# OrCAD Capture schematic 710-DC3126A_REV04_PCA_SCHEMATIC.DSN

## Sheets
1 PAGE1
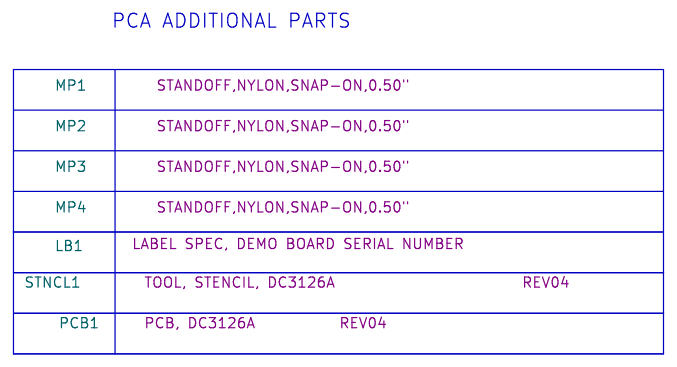
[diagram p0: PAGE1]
2 LT8686S: size Custom; title: MONOLITHIC STEP-DOWN REGULATOR; note: 42V QUAD, GANGABLE, SYNCHRONOUS
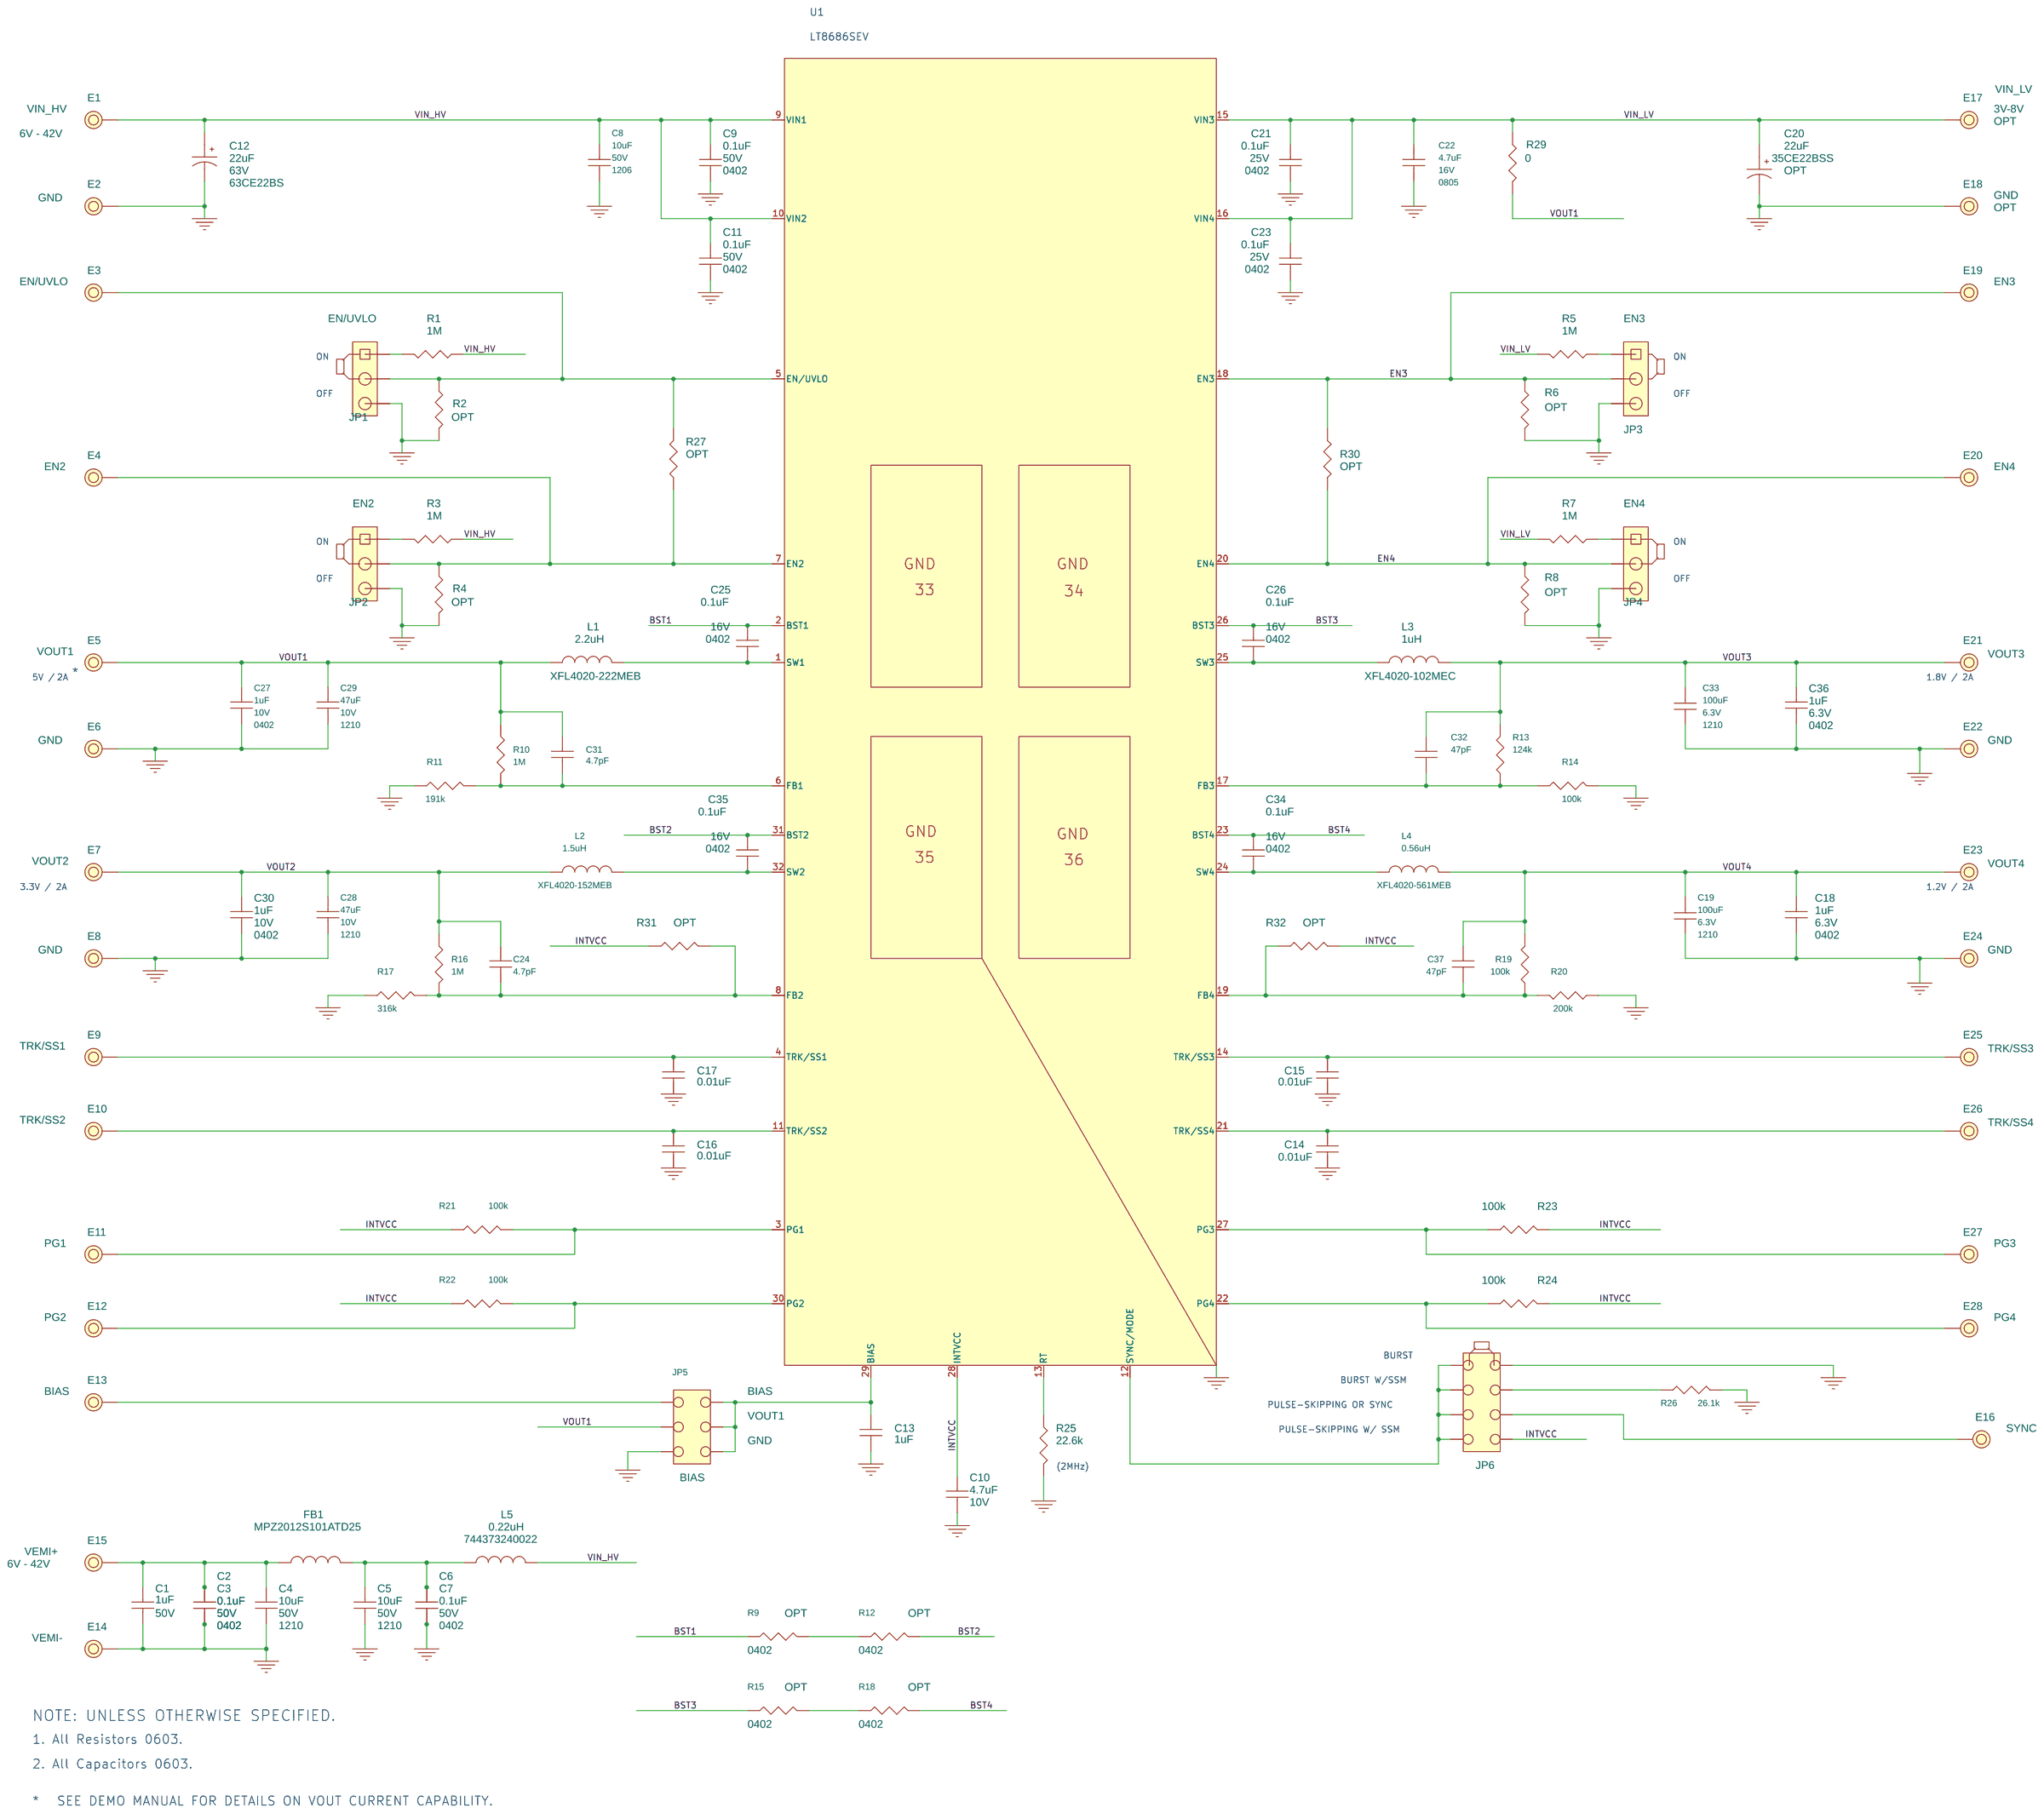
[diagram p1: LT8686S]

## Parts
sheet LT8686S
C1  1uF  [CC0603N]
C2  0.1uF  [CC0402N]
C3  0.1uF  [CC0402N]
C4  10uF  [CC1210N]
C5  10uF  [CC1210N]
C6  0.1uF  [CC0402N]
C7  0.1uF  [CC0402N]
C8  10uF  [CC1206N]
C9  0.1uF  [CC0402N]
C10  4.7uF  [CC0603N]
C11  0.1uF  [CC0402N]
C12  22uF  [SUNCON_CE-BS_6.3X7.7]
C13  1uF  [CC0603N]
C14  0.01uF  [CC0603N]
C15  0.01uF  [CC0603N]
C16  0.01uF  [CC0603N]
C17  0.01uF  [CC0603N]
C18  1uF  [CC0402N]
C19  100uF  [CC1210N]
C20  22uF  [SUNCON_CE-BSS_5X5.4]
C21  0.1uF  [CC0402N]
C22  4.7uF  [CC0805N]
C23  0.1uF  [CC0402N]
C24  4.7pF  [CC0603N]
C25  0.1uF  [CC0402N]
C26  0.1uF  [CC0402N]
C27  1uF  [CC0402N]
C28  47uF  [CC1210N]
C29  47uF  [CC1210N]
C30  1uF  [CC0402N]
C31  4.7pF  [CC0603N]
C32  47pF  [CC0603N]
C33  100uF  [CC1210N]
C34  0.1uF  [CC0402N]
C35  0.1uF  [CC0402N]
C36  1uF  [CC0402N]
C37  47pF  [CC0603N]
E1  TEST POINT  [MILLMAX2501]
E2  TEST POINT  [MILLMAX2501]
E3  TEST POINT  [MILLMAX2501]
E4  TEST POINT  [MILLMAX2501]
E5  TEST POINT  [MILLMAX2501]
E6  TEST POINT  [MILLMAX2501]
E7  TEST POINT  [MILLMAX2501]
E8  TEST POINT  [MILLMAX2501]
E9  TEST POINT  [MILLMAX2501]
E10  TEST POINT  [MILLMAX2501]
E11  TEST POINT  [MILLMAX2501]
E12  TEST POINT  [MILLMAX2501]
E13  TEST POINT  [MILLMAX2501]
E14  TEST POINT  [MILLMAX2501]
E15  TEST POINT  [MILLMAX2501]
E16  TEST POINT  [MILLMAX2501]
E17  TEST POINT  [MILLMAX2501]
E18  TEST POINT  [MILLMAX2501]
E19  TEST POINT  [MILLMAX2501]
E20  TEST POINT  [MILLMAX2501]
E21  TEST POINT  [MILLMAX2501]
E22  TEST POINT  [MILLMAX2501]
E23  TEST POINT  [MILLMAX2501]
E24  TEST POINT  [MILLMAX2501]
E25  TEST POINT  [MILLMAX2501]
E26  TEST POINT  [MILLMAX2501]
E27  TEST POINT  [MILLMAX2501]
E28  TEST POINT  [MILLMAX2501]
FB1  100 OHMS @100MHz  [IND0805N]
JP1  HDR  [HD1X3-079]
JP2  HDR  [HD1X3-079]
JP3  HDR  [HD1X3-079]
JP4  HDR  [HD1X3-079]
JP5  HDR  [HD2X3-079]
JP6  HDR  [HD2X4-079]
L1  2.2uH  [COILCRAFT-XFL4020]
L2  1.5uH  [COILCRAFT-XFL4020]
L3  1uH  [COILCRAFT-XFL4020]
L4  0.56uH  [COILCRAFT-XFL4020]
L5  0.22uH  [WURTH-4020]
R1  1M  [CR0603N]
R2  OPT  [CR0603N]
R3  1M  [CR0603N]
R4  OPT  [CR0603N]
R5  1M  [CR0603N]
R6  OPT  [CR0603N]
R7  1M  [CR0603N]
R8  OPT  [CR0603N]
R9  OPT  [CR0402N]
R10  1M  [CR0603N]
R11  191k  [CR0603N]
R12  OPT  [CR0402N]
R13  124k  [CR0603N]
R14  100k  [CR0603N]
R15  OPT  [CR0402N]
R16  1M  [CR0603N]
R17  316k  [CR0603N]
R18  OPT  [CR0402N]
R19  100k  [CR0603N]
R20  200k  [CR0603N]
R21  100k  [CR0603N]
R22  100k  [CR0603N]
R23  100k  [CR0603N]
R24  100k  [CR0603N]
R25  22.6k  [CR0603N]
R26  26.1k  [CR0603N]
R27  OPT  [CR0603N]
R29  0  [VISHAY-WSL_9-0603]
R30  OPT  [CR0603N]
R31  0  [CR0603N]
R32  0  [CR0603N]
U1  LT8686SEV  [LTC-LQFN-32-1680]
XJP1  SHUNT
XJP2  SHUNT
XJP3  SHUNT
XJP4  SHUNT
XJP5  SHUNT
XJP6  SHUNT
sheet PAGE1
LB1  LABEL  [895-0154_REV01]
MP1  STANDOFF  [KEYSTONE_8829-8834]
MP2  STANDOFF  [KEYSTONE_8829-8834]
MP3  STANDOFF  [KEYSTONE_8829-8834]
MP4  STANDOFF  [KEYSTONE_8829-8834]
PCB1  PCB, DC3126A
STNCL1  TOOL, STENCIL, DC3126A

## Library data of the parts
C1 C13 = CAP: CAP.,1uF,X5R,50V,10%,0603,AEC-Q200, NO SUBS. ALLOWED; CLASS: DISCRETE; Dielectric Type: X5R; FPLIST: CC0603N,CC0603L,CC0603M; Inventory Qty: 19670; Manufacturer: MURATA; Manufacturer PN: GRT188R61H105KE13D; PART_NUMBER: 150-0686; Package Size: 0603; Package Type: SMD; Rated Voltage: 50V; Tolerance: 10%
C2 C3 C6 C7 C9 C11 = CAP: CAP.,0.1uF,X7R,50V,10%,0402,AEC-Q200, NO SUBS. ALLOWED; CLASS: DISCRETE; Dielectric Type: X7R; FPLIST: CC0402N,CC0402L,CC0402M; Inventory Qty: 11376; Manufacturer: MURATA; Manufacturer PN: GCM155R71H104KE02D; PART_NUMBER: 150-2353; Package Size: 0402; Rated Voltage: 50V; Tolerance: 10%
C4 C5 = CAP: CAP.,10uF,X7R,50V,10%,1210,NO SUBS. ALLOWED; CLASS: DISCRETE; Dielectric Type: X7R; FPLIST: CC1210N,CC1210L,CC1210M; Inventory Qty: 191942; Manufacturer: MURATA; Manufacturer PN: GRM32ER71H106KA12L; PART_NUMBER: 150-3043; Package Size: 1210; Package Type: SMD; Rated Voltage: 50V; Tolerance: 10%
C8 = CAP: CAP.,10uF,X7R,50V,10%,1206; CLASS: DISCRETE; Dielectric Type: X7R; FPLIST: CC1206N,CC1206L,CC1206M; Inventory Qty: 4760; Manufacturer: SAMSUNG; Manufacturer PN: CL31B106KBHNNNE; PART_NUMBER: 150-1796; Package Size: 1206; Package Type: SMD; Rated Voltage: 50V; Tolerance: 10%
C10 = CAP: CAP.,4.7uF,X5R,10V,10%,0603; CLASS: DISCRETE; Dielectric Type: X5R; FPLIST: CC0603N,CC0603L,CC0603M; Inventory Qty: 20774; Manufacturer: AVX; Manufacturer PN: 0603ZD475KAT2A; PART_NUMBER: 150-3050; Package Size: 0603; Rated Voltage: 10V; Tolerance: 10%
C12 = CAP_P: CAP.,22uF,ALUM ELECT,63V,20%,6.3x7.7mm,SMD,RADIAL,CE-BS Series,AEC-Q200; CLASS: DISCRETE; Dielectric Type: ALUM ELECT; FPLIST: SUNCON_CE-BS_6.3X7.7,SUNCON_CE-BS_6-3X7-7; Inventory Qty: 35661; Manufacturer: SUN ELECTRONIC INDUSTRIES CORP; Manufacturer PN: 63CE22BS; PART_NUMBER: 150-3334; Package Size: 6.3x7.7mm,SMD,RADIAL; Rated Voltage: 63V; Tolerance: 20%
C14-C17 = CAP: CAP.,0.01uF,X7R,25V,10%,0603; CLASS: DISCRETE; Dielectric Type: X7R; FPLIST: CC0603N,CC0603L,CC0603M; Inventory Qty: 51504; Manufacturer: AVX; Manufacturer PN: 06033C103KAT2A; PART_NUMBER: 150-3341; Package Size: 0603; Package Type: SMD; Rated Voltage: 25V; Tolerance: 10%
C18 C36 = CAP: CAP.,1uF,X7R,6.3V,10%,0402; CLASS: DISCRETE; Dielectric Type: X7R; FPLIST: CC0402N,CC0402L,CC0402M; Inventory Qty: 20000; Manufacturer: MURATA; Manufacturer PN: GRM155R70J105KA12D; PART_NUMBER: 150-2328; Package Size: 0402; Rated Voltage: 6.3V; Tolerance: 10%
C19 C33 = CAP: CAP.,100uF,X7S,6.3V,20%,1210; CLASS: DISCRETE; Dielectric Type: X7S; FPLIST: CC1210N,CC1210L,CC1210M; Inventory Qty: 500; Manufacturer: MURATA; Manufacturer PN: GRM32EC70J107ME15L; PART_NUMBER: 150-2396; Package Size: 1210; Rated Voltage: 6.3V; Temperature Coefficient: X7S; Tolerance: 20%
C20 = CAP_P: CAP.,22uF,35V,20%,5x5.4mm,SMD,RADIAL,CE-BSS Series,AEC-Q200; BOM Notes: OPT; CLASS: DISCRETE; Dielectric Type: ALUM ELECT; FPLIST: SUNCON_CE-BSS_5X5.4,SUNCON_CE-BSS_5X5-4; Inventory Qty: 8056; Manufacturer: SUN ELECTRONIC INDUSTRIES CORP; Manufacturer PN: 35CE22BSS; PART_NUMBER: 150-0491; Package Size: 5x5.4mm,SMD,RADIAL; Rated Voltage: 35V; Tolerance: 20%
C21 C23 = CAP: CAP.,0.1uF,X7R,25V,10%,0402,AEC-Q200; CLASS: DISCRETE; Dielectric Type: X7R; FPLIST: CC0402N,CC0402L,CC0402M; Inventory Qty: 22030; Manufacturer: MURATA; Manufacturer PN: GCM155R71E104KE02D; PART_NUMBER: 150-1756; Package Size: 0402; Rated Voltage: 25V; Temperature Coefficient: X7R; Tolerance: 10%
C22 = CAP: CAP.,4.7uF,X7R,16V,20%,0805,AEC-Q200; CLASS: DISCRETE; Dielectric Type: X7R; FPLIST: CC0805N,CC0805L,CC0805M; Inventory Qty: 0; Manufacturer: Taiyo Yuden; Manufacturer PN: MCASE21GAB7475MTNA01; PART_NUMBER: 150-1025; Package Size: 0805; Rated Voltage: 16V; Tolerance: 20%
C24 C31 = CAP: CAP.,4.7pF,C0G,25V,10%,0603; CLASS: DISCRETE; Dielectric Type: C0G; FPLIST: CC0603N,CC0603L,CC0603M; Inventory Qty: 24942; Manufacturer: AVX; Manufacturer PN: 06033A4R7KAT2A; PART_NUMBER: 150-0381; Package Size: 0603; Rated Voltage: 25V; Tolerance: 10%
C25 C26 C34 C35 = CAP: CAP.,0.1uF,X7R,16V,10%,0402,AEC-Q200; CLASS: DISCRETE; Dielectric Type: X7R; FPLIST: CC0402N,CC0402L,CC0402M; Inventory Qty: 23025; Manufacturer: MURATA; Manufacturer PN: GCM155R71C104KA55D; PART_NUMBER: 150-0506; Package Size: 0402; Rated Voltage: 16V; Tolerance: 10%
C27 C30 = CAP: CAP.,1uF,X5R,10V,10%,0402; CLASS: DISCRETE; Dielectric Type: X5R; FPLIST: CC0402N,CC0402L,CC0402M; Inventory Qty: 110817; Manufacturer: MURATA; Manufacturer PN: GRM155R61A105KE15D; PART_NUMBER: 150-3493; Package Size: 0402; Rated Voltage: 10V; Tolerance: 10%
C28 C29 = CAP: CAP.,47uF,X7R,10V,10%,1210,NO SUBS. ALLOWED; CLASS: DISCRETE; Dielectric Type: X7R; FPLIST: CC1210N,CC1210L,CC1210M; Inventory Qty: 0; Manufacturer: MURATA; Manufacturer PN: GRM32ER71A476KE15L; PART_NUMBER: 150-0981; Package Size: 1210; Package Type: SMD; Part Reference_1: C255 (OPT); Rated Voltage: 10V; Tolerance: 10%
C32 C37 = CAP: CAP.,47pF,C0G,25V,10%,0603; CLASS: DISCRETE; Dielectric Type: C0G; FPLIST: CC0603N,CC0603L,CC0603M; Inventory Qty: 3750; Manufacturer: AVX; Manufacturer PN: 06033A470KAT2A; PART_NUMBER: 150-3110; Package Size: 0603; Rated Voltage: 25V; Tolerance: 10%
E1 = TESTPOINT_.219_MILL-MAX_2501: TEST POINT,TURRET,0.094" MTG. HOLE,PCB 0.062" THK; 10th Part Field: 10th???; 1th Part Field: 6V - 42V; 9th Part Field: VIN_HV; CLASS: IO; FPLIST: MILLMAX2501,MILLMAX2501-2; Inventory Qty: 823526; Manufacturer: MILL-MAX; Manufacturer PN: 2501-2-00-80-00-00-07-0; PART_NUMBER: 260-0003
E2 E6 E8 = TESTPOINT_.219_MILL-MAX_2501: TEST POINT,TURRET,0.094" MTG. HOLE,PCB 0.062" THK; 10th Part Field: 10th???; 9th Part Field: GND; CLASS: IO; FPLIST: MILLMAX2501,MILLMAX2501-2; Inventory Qty: 823526; Manufacturer: MILL-MAX; Manufacturer PN: 2501-2-00-80-00-00-07-0; PART_NUMBER: 260-0003
E3 = TESTPOINT_.219_MILL-MAX_2501: TEST POINT,TURRET,0.094" MTG. HOLE,PCB 0.062" THK; 10th Part Field: 10th???; 9th Part Field: EN/UVLO; CLASS: IO; FPLIST: MILLMAX2501,MILLMAX2501-2; Inventory Qty: 823526; Manufacturer: MILL-MAX; Manufacturer PN: 2501-2-00-80-00-00-07-0; PART_NUMBER: 260-0003
E4 = TESTPOINT_.219_MILL-MAX_2501: TEST POINT,TURRET,0.094" MTG. HOLE,PCB 0.062" THK; 10th Part Field: 10th???; 9th Part Field: EN2; CLASS: IO; FPLIST: MILLMAX2501,MILLMAX2501-2; Inventory Qty: 823526; Manufacturer: MILL-MAX; Manufacturer PN: 2501-2-00-80-00-00-07-0; PART_NUMBER: 260-0003
E5 = TESTPOINT_.219_MILL-MAX_2501: TEST POINT,TURRET,0.094" MTG. HOLE,PCB 0.062" THK; 10th Part Field: 10th???; 9th Part Field: VOUT1; CLASS: IO; FPLIST: MILLMAX2501,MILLMAX2501-2; Inventory Qty: 823526; Manufacturer: MILL-MAX; Manufacturer PN: 2501-2-00-80-00-00-07-0; PART_NUMBER: 260-0003
E7 = TESTPOINT_.219_MILL-MAX_2501: TEST POINT,TURRET,0.094" MTG. HOLE,PCB 0.062" THK; 10th Part Field: 10th???; 9th Part Field: VOUT2; CLASS: IO; FPLIST: MILLMAX2501,MILLMAX2501-2; Inventory Qty: 823526; Manufacturer: MILL-MAX; Manufacturer PN: 2501-2-00-80-00-00-07-0; PART_NUMBER: 260-0003
E9 = TESTPOINT_.219_MILL-MAX_2501: TEST POINT,TURRET,0.094" MTG. HOLE,PCB 0.062" THK; 10th Part Field: 10th???; 9th Part Field: TRK/SS1; CLASS: IO; FPLIST: MILLMAX2501,MILLMAX2501-2; Inventory Qty: 823526; Manufacturer: MILL-MAX; Manufacturer PN: 2501-2-00-80-00-00-07-0; PART_NUMBER: 260-0003
E10 = TESTPOINT_.219_MILL-MAX_2501: TEST POINT,TURRET,0.094" MTG. HOLE,PCB 0.062" THK; 10th Part Field: 10th???; 9th Part Field: TRK/SS2; CLASS: IO; FPLIST: MILLMAX2501,MILLMAX2501-2; Inventory Qty: 823526; Manufacturer: MILL-MAX; Manufacturer PN: 2501-2-00-80-00-00-07-0; PART_NUMBER: 260-0003
E11 = TESTPOINT_.219_MILL-MAX_2501: TEST POINT,TURRET,0.094" MTG. HOLE,PCB 0.062" THK; 10th Part Field: 10th???; 9th Part Field: PG1; CLASS: IO; FPLIST: MILLMAX2501,MILLMAX2501-2; Inventory Qty: 823526; Manufacturer: MILL-MAX; Manufacturer PN: 2501-2-00-80-00-00-07-0; PART_NUMBER: 260-0003
E12 = TESTPOINT_.219_MILL-MAX_2501: TEST POINT,TURRET,0.094" MTG. HOLE,PCB 0.062" THK; 10th Part Field: 10th???; 9th Part Field: PG2; CLASS: IO; FPLIST: MILLMAX2501,MILLMAX2501-2; Inventory Qty: 823526; Manufacturer: MILL-MAX; Manufacturer PN: 2501-2-00-80-00-00-07-0; PART_NUMBER: 260-0003
E13 = TESTPOINT_.219_MILL-MAX_2501: TEST POINT,TURRET,0.094" MTG. HOLE,PCB 0.062" THK; 10th Part Field: 10th???; 9th Part Field: BIAS; CLASS: IO; FPLIST: MILLMAX2501,MILLMAX2501-2; Inventory Qty: 823526; Manufacturer: MILL-MAX; Manufacturer PN: 2501-2-00-80-00-00-07-0; PART_NUMBER: 260-0003
E14 = TESTPOINT_.219_MILL-MAX_2501: TEST POINT,TURRET,0.094" MTG. HOLE,PCB 0.062" THK; 10th Part Field: 10th???; 9th Part Field: VEMI-; CLASS: IO; FPLIST: MILLMAX2501,MILLMAX2501-2; Inventory Qty: 823526; Manufacturer: MILL-MAX; Manufacturer PN: 2501-2-00-80-00-00-07-0; PART_NUMBER: 260-0003
E15 = TESTPOINT_.219_MILL-MAX_2501: TEST POINT,TURRET,0.094" MTG. HOLE,PCB 0.062" THK; 10th Part Field: 10th???; 1th Part Field: 6V - 42V; 9th Part Field: VEMI+; CLASS: IO; FPLIST: MILLMAX2501,MILLMAX2501-2; Inventory Qty: 823526; Manufacturer: MILL-MAX; Manufacturer PN: 2501-2-00-80-00-00-07-0; PART_NUMBER: 260-0003
E16 = TESTPOINT_.219_MILL-MAX_2501: TEST POINT,TURRET,0.094" MTG. HOLE,PCB 0.062" THK; 10th Part Field: 10th???; 1th Part Field: 3V - 8V; 9th Part Field: SYNC; CLASS: IO; FPLIST: MILLMAX2501,MILLMAX2501-2; Inventory Qty: 823526; Manufacturer: MILL-MAX; Manufacturer PN: 2501-2-00-80-00-00-07-0; PART_NUMBER: 260-0003
E17 = TESTPOINT_.219_MILL-MAX_2501: TEST POINT,TURRET,0.094" MTG. HOLE,PCB 0.062" THK; 10th Part Field: 10th???; 1ST PART FIELD: OPT; 1th Part Field: 3V-8V; 9th Part Field: VIN_LV; CLASS: IO; FPLIST: MILLMAX2501,MILLMAX2501-2; Inventory Qty: 823526; Manufacturer: MILL-MAX; Manufacturer PN: 2501-2-00-80-00-00-07-0; PART_NUMBER: 260-0003
E18 = TESTPOINT_.219_MILL-MAX_2501: TEST POINT,TURRET,0.094" MTG. HOLE,PCB 0.062" THK; 10th Part Field: 10th???; 1ST PART FIELD: OPT; 9th Part Field: GND; CLASS: IO; FPLIST: MILLMAX2501,MILLMAX2501-2; Inventory Qty: 823526; Manufacturer: MILL-MAX; Manufacturer PN: 2501-2-00-80-00-00-07-0; PART_NUMBER: 260-0003
E19 = TESTPOINT_.219_MILL-MAX_2501: TEST POINT,TURRET,0.094" MTG. HOLE,PCB 0.062" THK; 10th Part Field: 10th???; 9th Part Field: EN3; CLASS: IO; FPLIST: MILLMAX2501,MILLMAX2501-2; Inventory Qty: 823526; Manufacturer: MILL-MAX; Manufacturer PN: 2501-2-00-80-00-00-07-0; PART_NUMBER: 260-0003
E20 = TESTPOINT_.219_MILL-MAX_2501: TEST POINT,TURRET,0.094" MTG. HOLE,PCB 0.062" THK; 10th Part Field: 10th???; 1th Part Field: 3V - 8V; 9th Part Field: EN4; CLASS: IO; FPLIST: MILLMAX2501,MILLMAX2501-2; Inventory Qty: 823526; Manufacturer: MILL-MAX; Manufacturer PN: 2501-2-00-80-00-00-07-0; PART_NUMBER: 260-0003
E21 = TESTPOINT_.219_MILL-MAX_2501: TEST POINT,TURRET,0.094" MTG. HOLE,PCB 0.062" THK; 10th Part Field: 10th???; 1th Part Field: 3V - 8V; 9th Part Field: VOUT3; CLASS: IO; FPLIST: MILLMAX2501,MILLMAX2501-2; Inventory Qty: 823526; Manufacturer: MILL-MAX; Manufacturer PN: 2501-2-00-80-00-00-07-0; PART_NUMBER: 260-0003
E22 E24 = TESTPOINT_.219_MILL-MAX_2501: TEST POINT,TURRET,0.094" MTG. HOLE,PCB 0.062" THK; 10th Part Field: 10th???; 1th Part Field: 3V - 8V; 9th Part Field: GND; CLASS: IO; FPLIST: MILLMAX2501,MILLMAX2501-2; Inventory Qty: 823526; Manufacturer: MILL-MAX; Manufacturer PN: 2501-2-00-80-00-00-07-0; PART_NUMBER: 260-0003
E23 = TESTPOINT_.219_MILL-MAX_2501: TEST POINT,TURRET,0.094" MTG. HOLE,PCB 0.062" THK; 10th Part Field: 10th???; 1th Part Field: 3V - 8V; 9th Part Field: VOUT4; CLASS: IO; FPLIST: MILLMAX2501,MILLMAX2501-2; Inventory Qty: 823526; Manufacturer: MILL-MAX; Manufacturer PN: 2501-2-00-80-00-00-07-0; PART_NUMBER: 260-0003
E25 = TESTPOINT_.219_MILL-MAX_2501: TEST POINT,TURRET,0.094" MTG. HOLE,PCB 0.062" THK; 10th Part Field: 10th???; 1th Part Field: 3V - 8V; 9th Part Field: TRK/SS3; CLASS: IO; FPLIST: MILLMAX2501,MILLMAX2501-2; Inventory Qty: 823526; Manufacturer: MILL-MAX; Manufacturer PN: 2501-2-00-80-00-00-07-0; PART_NUMBER: 260-0003
E26 = TESTPOINT_.219_MILL-MAX_2501: TEST POINT,TURRET,0.094" MTG. HOLE,PCB 0.062" THK; 10th Part Field: 10th???; 1th Part Field: 3V - 8V; 9th Part Field: TRK/SS4; CLASS: IO; FPLIST: MILLMAX2501,MILLMAX2501-2; Inventory Qty: 823526; Manufacturer: MILL-MAX; Manufacturer PN: 2501-2-00-80-00-00-07-0; PART_NUMBER: 260-0003
E27 = TESTPOINT_.219_MILL-MAX_2501: TEST POINT,TURRET,0.094" MTG. HOLE,PCB 0.062" THK; 10th Part Field: 10th???; 1th Part Field: 3V - 8V; 9th Part Field: PG3; CLASS: IO; FPLIST: MILLMAX2501,MILLMAX2501-2; Inventory Qty: 823526; Manufacturer: MILL-MAX; Manufacturer PN: 2501-2-00-80-00-00-07-0; PART_NUMBER: 260-0003
E28 = TESTPOINT_.219_MILL-MAX_2501: TEST POINT,TURRET,0.094" MTG. HOLE,PCB 0.062" THK; 10th Part Field: 10th???; 1th Part Field: 3V - 8V; 9th Part Field: PG4; CLASS: IO; FPLIST: MILLMAX2501,MILLMAX2501-2; Inventory Qty: 823526; Manufacturer: MILL-MAX; Manufacturer PN: 2501-2-00-80-00-00-07-0; PART_NUMBER: 260-0003
FB1 = IND: IND.,100 OHMS @100MHz,FERRITE BEAD,25%,4A,20mOHMS,0805,AEC-Q200; CLASS: DISCRETE; FPLIST: IND0805N,IND0805L,IND0805M; Inventory Qty: 0; Manufacturer: TDK; Manufacturer PN: MPZ2012S101ATD25; PART_NUMBER: 200-0403; Package Size: 0805; Tolerance: 25%
JP1 = 1X3_B: CONN.,HDR,MALE,1x3,2mm,VERT,ST,THT,NO SUBS. ALLOWED; 9th Part Field: EN/UVLO; CLASS: IO; Inventory Qty: 28997; Manufacturer: Wurth Elektronik; Manufacturer PN: 62000311121; PART_NUMBER: 250-0639
JP2 = 1X3_B: CONN.,HDR,MALE,1x3,2mm,VERT,ST,THT,NO SUBS. ALLOWED; 9th Part Field: EN2; CLASS: IO; Inventory Qty: 28997; Manufacturer: Wurth Elektronik; Manufacturer PN: 62000311121; PART_NUMBER: 250-0639
JP3 = 1X3_B: CONN.,HDR,MALE,1x3,2mm,VERT,ST,THT,NO SUBS. ALLOWED; 9th Part Field: EN3; CLASS: IO; Inventory Qty: 28997; Manufacturer: Wurth Elektronik; Manufacturer PN: 62000311121; PART_NUMBER: 250-0639
JP4 = 1X3_B: CONN.,HDR,MALE,1x3,2mm,VERT,ST,THT,NO SUBS. ALLOWED; 9th Part Field: EN4; CLASS: IO; Inventory Qty: 28997; Manufacturer: Wurth Elektronik; Manufacturer PN: 62000311121; PART_NUMBER: 250-0639
JP5 = HEADER_2X3_.079: CONN.,HDR,MALE,2x3,2mm,VERT,ST,THT; 1st Part Field: BIAS; 2nd Part Field: BIAS; 3rd Part Field: VOUT1; 4th Part Field: GND; CLASS: IO; Inventory Qty: 17651; Manufacturer: WURTH ELEKTRONIK; Manufacturer PN: 62000621121; PART_NUMBER: 250-0483
JP6 = HEADER_2X4_.079: CONN.,HDR,MALE,2x4,2mm,VERT,ST,THT; 1st Part Field: SYNC; CLASS: IO; Inventory Qty: 6305; Manufacturer: WURTH ELEKTRONIK; Manufacturer PN: 62000821121; PART_NUMBER: 250-0581
L1 = IND: IND.,2.2uH,PWR,SHIELDED,20%,8A,23.5mOHMS,4.3x4.3mm,AEC-Q200; CLASS: DISCRETE; Inventory Qty: 506; Manufacturer: COILCRAFT; Manufacturer PN: XFL4020-222MEB; PART_NUMBER: 200-0255; Package Size: 4.3x4.3mm; Tolerance: 20%
L2 = IND: IND.,1.5uH,PWR,20%,9.1A,15.8mOHMS,SMD,AEC-Q200,SHIELDED; CLASS: DISCRETE; Inventory Qty: 0; Manufacturer: COILCRAFT; Manufacturer PN: XFL4020-152MEB; PART_NUMBER: 200-0367; Package Size: SMD; Tolerance: 20%
L3 = IND: IND.,1uH,PWR,SHIELDED,20%,11A,11.9mOHMS,SMD,AEC-Q200; CLASS: DISCRETE; Inventory Qty: 0; Manufacturer: COILCRAFT; Manufacturer PN: XFL4020-102MEC; PART_NUMBER: 200-0404; Package Size: SMD; Tolerance: 20%
L4 = IND: IND.,0.56uH,PWR,20%,6A,5.53mOHMS,SMD,AEC-Q200; CLASS: DISCRETE; Inventory Qty: 0; Manufacturer: COILCRAFT; Manufacturer PN: XFL4020-561MEB; PART_NUMBER: 200-0421; Package Size: SMD; Tolerance: 20%
L5 = IND: IND.,0.22uH,PWR,SHIELDED,30%,9.5A,7.3mOHMS,4020; CLASS: DISCRETE; FPLIST: WURTH-4020,WURTH-744373240022; Inventory Qty: 418; Manufacturer: WURTH ELEKTRONIK; Manufacturer PN: 744373240022; PART_NUMBER: 200-0481; Package Size: 4020; Tolerance: 30%
R1 R3 R5 R7 R10 R16 = RES: RES.,1M OHM,1%,1/10W,0603; CLASS: DISCRETE; FPLIST: CR0603N,CR0603L,CR0603M; Inventory Qty: 165718; Manufacturer: VISHAY; Manufacturer PN: CRCW06031M00FKEA; PART_NUMBER: 100-0335; Package Size: 0603; Rated Power: 1/10W; Temperature Coefficient: 100ppm; Tolerance: 1%
R2 R4 R6 R8 R27 R30 = RES: RES., OPTION, 0603; CLASS: DISCRETE; FPLIST: CR0603N,CR0603L,CR0603M; PART_NUMBER: 100-2374; Package Size: 0603
R9 R12 R15 R18 = RES: RES., OPTION, 0402; CLASS: DISCRETE; FPLIST: CR0402N,CR0402L,CR0402M; PART_NUMBER: 100-0357; Package Size: 0402
R11 = RES: RES.,191k OHMS,1%,1/10W,0603,AEC-Q200; CLASS: DISCRETE; FPLIST: CR0603N,CR0603L,CR0603M; Inventory Qty: 10000; Manufacturer: KOA SPEER; Manufacturer PN: RK73H1JTTD1913F; PART_NUMBER: 100-1556; Package Size: 0603; Rated Power: 1/10W; Temperature Coefficient: +/-100ppm; Tolerance: 1%
R13 = RES: RES.,124k OHMS,1%,1/10W,0603,AEC-Q200; CLASS: DISCRETE; FPLIST: CR0603N,CR0603L,CR0603M; Inventory Qty: 90015; Manufacturer: PANASONIC; Manufacturer PN: ERJ3EKF1243V; PART_NUMBER: 100-0224; Package Size: 0603; Rated Power: 1/10W; Temperature Coefficient: 100ppm; Tolerance: 1%
R14 R19 R21-R24 = RES: RES.,100k OHMS,1%,1/10W,0603,AEC-Q200; CLASS: DISCRETE; FPLIST: CR0603N,CR0603L,CR0603M; Inventory Qty: 185604; Manufacturer: VISHAY; Manufacturer PN: CRCW0603100KFKEA; PART_NUMBER: 100-0343; Package Size: 0603; Rated Power: 1/10W; Temperature Coefficient: +/-100ppm; Tolerance: 1%
R17 = RES: RES.,316k OHMS,1%,1/10W,0603,AEC-Q200; CLASS: DISCRETE; FPLIST: CR0603N,CR0603L,CR0603M; Inventory Qty: 12794; Manufacturer: NIC; Manufacturer PN: NRC06F3163TRF; PART_NUMBER: 100-2591; Package Size: 0603; Rated Power: 1/10W; Temperature Coefficient: 100ppm; Tolerance: 1%
R20 = RES: RES.,200k OHMS,1%,1/10W,0603; CLASS: DISCRETE; FPLIST: CR0603N,CR0603L,CR0603M; Inventory Qty: 116370; Manufacturer: NIC; Manufacturer PN: NRC06F2003TRF; PART_NUMBER: 100-2378; Package Size: 0603; Rated Power: 1/10W; Temperature Coefficient: 100ppm/C; Tolerance: 1%
R25 = RES: RES.,22.6k OHMS,1%,1/10W,0603; CLASS: DISCRETE; FPLIST: CR0603N,CR0603L,CR0603M; Inventory Qty: 5000; Manufacturer: NIC; Manufacturer PN: NRC06F2262TRF; PART_NUMBER: 100-2365; Package Size: 0603; Rated Power: 1/10W; Temperature Coefficient: 100ppm/C; Tolerance: 1%
R26 = RES: RES.,26.1k OHMS,1%,1/10W,0603,AEC-Q200; CLASS: DISCRETE; FPLIST: CR0603N,CR0603L,CR0603M; Inventory Qty: 34752; Manufacturer: NIC; Manufacturer PN: NRC06F2612TRF; PART_NUMBER: 100-0855; Package Size: 0603; Rated Power: 1/10W; Temperature Coefficient: 100ppm; Tolerance: 1%
R29 = RES: RES.,0 OHM,JUMPER,45A,0603,COPPER,SENSE; CLASS: DISCRETE; FPLIST: VISHAY-WSL_9-0603,CR0603N,CR0603L,CR0603M; Inventory Qty: 2000; Manufacturer: VISHAY; Manufacturer PN: WSL060300000ZEA9; PART_NUMBER: 100-1494; Package Size: 0603; Rated Power: 45A; Temperature Coefficient: +/-3900ppm; Tolerance: JUMPER
R31 R32 = RES: RES.,0 OHM,1/10W,0603,AEC-Q200; 1ST PART FIELD: OPT; CLASS: DISCRETE; FPLIST: CR0603N,CR0603L,CR0603M; Inventory Qty: 676258; Manufacturer: VISHAY; Manufacturer PN: CRCW06030000Z0EA; PART_NUMBER: 100-0009; Package Size: 0603; Rated Power: 1/10W
U1 = LT8686SEV: IC,42V QUAD SYNC. MONOLITHIC STEP-DOWN REGULATOR,LQFN-32; CLASS: IC; Inventory Qty: 0; Manufacturer: ANALOG DEVICES; Manufacturer PN: LT8686SJV#PBF; PART_NUMBER: LT8686SJV#PBF; Package Type: LQFN-32
XJP1-XJP6 = SHUNT_2MM: CONN.,SHUNT,FEMALE,2-POS,2mm; CLASS: IO; Inventory Qty: 64675; Manufacturer: Wurth Elektronik; Manufacturer PN: 60800213421; PART_NUMBER: 250-0485
LB1 = BLANK_LABEL: LABEL SPEC, DEMO BOARD SERIAL NUMBER; Inventory Qty: 0; Manufacturer: BRADY; Manufacturer PN: THT-96-717-10; PART_NUMBER: 895-0154
MP1-MP4 = BLANK_MECHANICAL_PART: STANDOFF,NYLON,SNAP-ON,0.50"; CLASS: DISCRETE; Inventory Qty: 214842; Manufacturer: KEYSTONE; Manufacturer PN: 8833; PART_NUMBER: 763-0007
PCB1 = BLANK_PCB_PART: BOM Notes: REV04; CLASS: DISCRETE; Inventory Qty: 0; Manufacturer: ADI APPROVED SUPPLIER; Manufacturer PN: 600-DC3126A; PART_NUMBER: 600-DC3126A
STNCL1 = BLANK_STENCIL_PART: BOM Notes: REV04; CLASS: DISCRETE; Inventory Qty: 0; Manufacturer: ADI APPROVED SUPPLIER; Manufacturer PN: 830-DC3126A; PART_NUMBER: 830-DC3126A

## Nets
GND: C1.2 C2.2 C3.2 C4.2 C5.2 C6.2 C7.2 C8.2 C9.2 C10.2 C11.2 C12.2 C13.2 C14.2 C15.2 C16.2 C17.2 C18.2 C19.1 C20.2 C21.2 C22.2 C23.2 C27.2 C28.2 C29.2 C30.2 C33.1 C36.2 E2.1 E6.1 E8.1 E14.1 E18.1 E22.1 E24.1 JP1.3 JP2.3 JP3.3 JP4.3 JP5.5 JP6.2 R2.2 R4.2 R6.2 R8.2 R11.1 R14.2 R17.1 R20.2 R25.2 R26.2
VIN_HV: C8.1 C9.1 C11.1 C12.1 E1.1 L5.2 R1.1 R3.1 U1.9(VIN1) U1.10(VIN2)
VIN_LV: C20.1 C21.1 C22.1 C23.1 E17.1 R5.2 R7.2 R29.1 U1.15(VIN3) U1.16(VIN4)
BST1: C25.1 R9.1 U1.2(BST1)
BST2: C35.1 R12.2 U1.31(BST2)
BST3: C26.1 R15.1 U1.26(BST3)
BST4: C34.1 R18.2 U1.23(BST4)
EN3: E19.1 JP3.2 R6.1 R30.1 U1.18(EN3)
EN4: E20.1 JP4.2 R8.1 R30.2 U1.20(EN4)
INTVCC: C10.1 JP6.8 R21.2 R22.2 R23.2 R24.2 R31.1 R32.2 U1.28(INTVCC)
VOUT1: C27.1 C29.1 C31.1 E5.1 JP5.3 L1.2 R10.1 R29.2
VOUT2: C24.1 C28.1 C30.1 E7.1 L2.2 R16.1
VOUT3: C32.1 C33.2 C36.1 E21.1 L3.2 R13.1
VOUT4: C18.1 C19.2 C37.1 E23.1 L4.2 R19.1
N863302: E3.1 JP1.2 R2.1 R27.1 U1.5(EN/UVLO)
N863406: JP1.1 R1.2
N863422: JP3.1 R5.1
N863606: E4.1 JP2.2 R4.1 R27.2 U1.7(EN2)
N863702: JP2.1 R3.2
N863718: JP4.1 R7.1
N863984: C25.2 L1.1 U1.1(SW1)
N864000: C26.2 L3.1 U1.25(SW3)
N864488: C31.2 R10.2 R11.2 U1.6(FB1)
N864500: C32.2 R13.2 R14.1 U1.17(FB3)
N864724: C35.2 L2.1 U1.32(SW2)
N864736: C34.2 L4.1 U1.24(SW4)
N865228: C24.2 R16.2 R17.2 R31.2 U1.8(FB2)
N865260: C37.2 R19.2 R20.1 R32.1 U1.19(FB4)
N865368: C17.1 E9.1 U1.4(TRK/SS1)
N865376: C15.1 E25.1 U1.14(TRK/SS3)
N865456: C16.1 E10.1 U1.11(TRK/SS2)
N865464: C14.1 E26.1 U1.21(TRK/SS4)
N865554: E11.1 R21.1 U1.3(PG1)
N865566: E27.1 R23.1 U1.27(PG3)
N865666: E12.1 R22.1 U1.30(PG2)
N865678: E28.1 R24.1 U1.22(PG4)
N865786: JP6.1 JP6.3 JP6.5 JP6.7 U1.12(SYNC/MODE)
N865816: C13.1 JP5.2 JP5.4 JP5.6 U1.29(BIAS)
N865824: R25.1 U1.13(RT)
N865852: E13.1 JP5.1
N912488: C1.1 C2.1 C3.1 C4.1 E15.1 FB1.1
N912516: C5.1 C6.1 C7.1 FB1.2 L5.1
N1409344: JP6.4 R26.1
N1410160: E16.1 JP6.6
N1521721: R9.2 R12.1
N1521737: R15.2 R18.1

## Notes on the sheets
sheet 1
- PCA ADDITIONAL PARTS
sheet 2
- U1
- LT8686SEV
- ON
- ON
- OFF
- OFF
- ON
- ON
- OFF
- OFF
- *
- 5V /
- 2A
- 1.8V / 2A
- 3.3V / 2A
- 1.2V / 2A
- BURST
- BURST W/SSM
- PULSE-SKIPPING OR SYNC
- PULSE-SKIPPING W/ SSM
- (2MHz)
- NOTE: UNLESS OTHERWISE SPECIFIED.
- 1. All Resistors 0603.
- 2. All Capacitors 0603.
- *
- SEE DEMO MANUAL FOR DETAILS ON VOUT CURRENT CAPABILITY.
